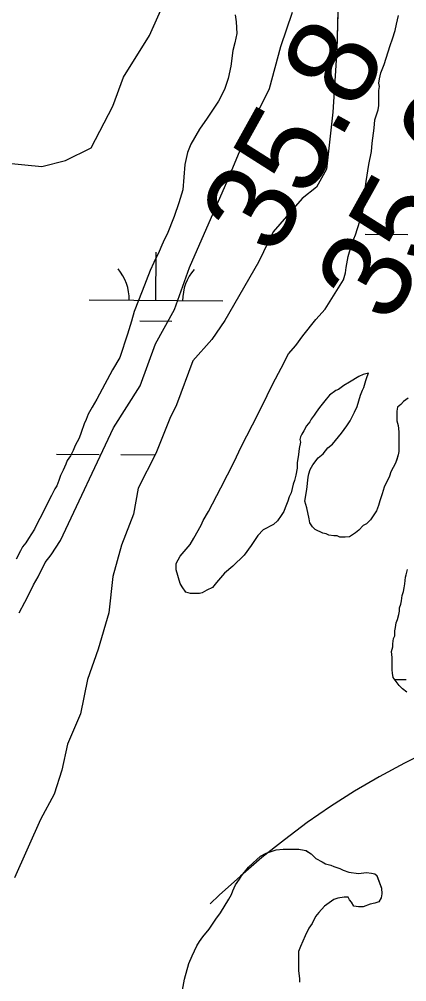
# Model space of a CAD drawing. Extents: x 3271442 to 3309282, y 752266 to 777610.
# Drawn here: x 3286138 to 3286428, y 766789 to 767508 of the extents above; entities that cross this region are included whole.
import ezdxf

# ---------------------------------------------------------------- set-up
doc = ezdxf.new("R2010")
doc.units = 0
for name, color, linetype in [('V-RIVR-RANG', 7, 'Continuous'), ('V-SITE-VEGE', 7, 'Continuous'), ('V-TOPO-MAJR', 7, 'Continuous'), ('V-TOPO-SHOR', 7, 'Continuous'), ('V-WETL-SWMP', 7, 'Continuous')]:
    doc.layers.add(name, color=color, linetype=linetype)

msp = doc.modelspace()

# ---------------------------------------------------------------- linework, layer by layer
at = {"layer": 'V-SITE-VEGE'}
for points in [[(3286126.68, 767401.28), (3286154.51, 767398.32), (3286172.15, 767402.8), (3286191.51, 767412.38), (3286207.55, 767443.57), (3286215.59, 767465.13), (3286235.04, 767496.31), (3286256.84, 767545.09), (3286266.64, 767579.72), (3286270.24, 767625.74), (3286269.25, 767663.82), (3286263.19, 767709.88), (3286273.59, 767750.75), (3286293.08, 767793.86), (3286306.85, 767823.93), (3286325.76, 767863.63), (3286346.42, 767912.99), (3286355.65, 767945.34)], [(3286376.57, 767531.75), (3286375.25, 767485.72), (3286372.22, 767439.13), (3286367.5, 767396.53), (3286360.05, 767382.92), (3286349.22, 767374.44), (3286327.52, 767349.52), (3286316.63, 767326.84), (3286291.45, 767283.18), (3286281.73, 767269.01), (3286267.46, 767253.16), (3286255.39, 767220.25), (3286250.23, 767210.04), (3286239.9, 767183.94), (3286226.72, 767157.85), (3286223.23, 767138.54), (3286214.04, 767115.28), (3286207.7, 767092), (3286204.74, 767064.74), (3286196.68, 767037.49), (3286188.63, 767014.79), (3286183.41, 766989.24), (3286173.66, 766966.55), (3286169.6, 766947.24), (3286163.84, 766929.08), (3286153.54, 766910.37), (3286134.04, 766866.69)], [(3286299.12, 767511.92), (3286300.07, 767506.56), (3286300.52, 767497.79), (3286299.03, 767490.98), (3286297.55, 767485.14), (3286296.04, 767473.45), (3286294.05, 767464.2), (3286291.1, 767455.93), (3286286.68, 767447.18), (3286278.34, 767434.55), (3286272.46, 767426.29), (3286266.08, 767415.11), (3286263.62, 767408.79), (3286261.64, 767400.03), (3286260.1, 767381.03), (3286257.14, 767371.3), (3286253.68, 767361.08), (3286248.27, 767347.95), (3286246.31, 767344.07), (3286244.34, 767339.69), (3286242.37, 767334.83), (3286238.44, 767326.56), (3286235.49, 767320.73), (3286229.58, 767305.16), (3286223.68, 767290.08), (3286221.7, 767282.78), (3286218.73, 767273.05), (3286212.82, 767255.54), (3286207.42, 767246.3), (3286197.6, 767228.32), (3286195.64, 767224.43), (3286192.21, 767218.6), (3286189.26, 767213.25), (3286187.78, 767209.36), (3286186.31, 767205.95), (3286183.85, 767199.63), (3286182.37, 767195.26), (3286179.42, 767189.91), (3286177.95, 767186.02), (3286175.98, 767182.13), (3286173.53, 767178.73), (3286172.54, 767175.81), (3286170.58, 767171.43), (3286168.61, 767167.54), (3286167.14, 767163.65), (3286165.66, 767159.76), (3286164.19, 767157.33), (3286161.73, 767152.47), (3286156.82, 767142.74), (3286154.36, 767137.4), (3286151.91, 767133.02), (3286148.96, 767127.19), (3286144.55, 767120.38), (3286142.59, 767116.98), (3286140.14, 767114.07), (3286138.67, 767111.15), (3286135.23, 767104.83)], [(3286137.5, 767064.87), (3286141.92, 767072.65), (3286144.38, 767077.51), (3286148.31, 767085.78), (3286151.74, 767091.61), (3286157.14, 767102.31), (3286161.55, 767108.13), (3286168.42, 767118.82), (3286208.16, 767203.16), (3286228.09, 767234.5), (3286239.49, 767265.84), (3286253.73, 767291.49), (3286265.12, 767322.83), (3286293.6, 767388.36), (3286307.84, 767422.55), (3286324.93, 767456.74), (3286333.47, 767488.08), (3286342.01, 767513.72)], [(3286258.01, 767086.63), (3286255.13, 767096.87), (3286255.15, 767101.74), (3286258.09, 767107.09), (3286265.44, 767115.83), (3286268.38, 767120.69), (3286273.78, 767130.41), (3286275.25, 767133.81), (3286279.18, 767140.62), (3286288.51, 767158.12), (3286298.33, 767177.57), (3286303.73, 767188.75), (3286312.08, 767205.28), (3286318.96, 767218.4), (3286327.31, 767235.91), (3286333.69, 767247.57), (3286339.09, 767258.27), (3286344.48, 767264.58), (3286349.87, 767271.87), (3286359.66, 767284), (3286366.51, 767291.77), (3286380.24, 767313.64), (3286381.73, 767318.99), (3286382.23, 767322.89), (3286383.72, 767331.16), (3286384.71, 767334.57), (3286385.7, 767337.49), (3286386.69, 767341.38), (3286389.15, 767347.22), (3286392.6, 767357.43), (3286394.57, 767363.76), (3286396.06, 767371.06), (3286396.1, 767379.83), (3286397.1, 767387.13), (3286399.1, 767399.79), (3286401.09, 767409.53), (3286401.61, 767415.86), (3286403.11, 767427.06), (3286403.63, 767433.39), (3286406.09, 767440.68), (3286406.59, 767444.09), (3286406.61, 767448.48), (3286406.64, 767455.3), (3286407.14, 767458.22), (3286406.66, 767460.65), (3286407.16, 767464.06), (3286408.15, 767468.45), (3286410.62, 767474.77), (3286415.06, 767488.88), (3286417.03, 767493.74), (3286419, 767500.07), (3286419.99, 767504.93), (3286421.48, 767511.26)], [(3286421.67, 767199.96), (3286421.61, 767185.34), (3286421.12, 767182.91), (3286420.13, 767179.51), (3286419.14, 767176.58), (3286415.71, 767170.27), (3286414.72, 767166.86), (3286410.79, 767158.59), (3286409.3, 767153.73), (3286407.33, 767148.38), (3286406.35, 767144.97), (3286404.87, 767141.08), (3286403.4, 767138.65), (3286400.46, 767134.28), (3286397.52, 767131.37), (3286395.08, 767129.92), (3286391.66, 767126.52), (3286389.21, 767124.58), (3286384.81, 767121.68), (3286381.4, 767121.2), (3286377.51, 767121.22), (3286375.56, 767122.2), (3286373.13, 767122.21), (3286369.23, 767122.71), (3286367.29, 767123.7), (3286364.85, 767124.19), (3286359.02, 767127.14), (3286357.08, 767129.09), (3286355.14, 767132.03), (3286354.67, 767134.95), (3286352.75, 767143.24), (3286351.31, 767148.12), (3286352.81, 767156.88), (3286353.82, 767166.13), (3286354.31, 767168.57), (3286355.3, 767171.97), (3286357.27, 767175.38), (3286361.19, 767180.72), (3286365.1, 767183.62), (3286368.52, 767188), (3286371.95, 767190.91), (3286378.8, 767199.16), (3286382.72, 767204.5), (3286385.17, 767208.39), (3286388.61, 767214.71), (3286390.57, 767219.08), (3286393.04, 767227.36), (3286394.52, 767231.25), (3286395.5, 767233.19), (3286396.98, 767238.55), (3286397.97, 767241.46), (3286398.96, 767243.9), (3286395.06, 767242.94), (3286391.64, 767241.49), (3286384.8, 767237.13), (3286380.41, 767234.72), (3286376.5, 767231.81), (3286374.54, 767230.84), (3286369.66, 767227.45), (3286367.21, 767224.54), (3286362.31, 767218.23), (3286359.86, 767214.83), (3286358.39, 767212.4), (3286355.94, 767209.48), (3286354.96, 767207.54), (3286352.51, 767204.63), (3286350.55, 767200.74), (3286349.08, 767198.31), (3286348.1, 767196.36), (3286347.6, 767194.41), (3286348.08, 767192.46), (3286347.09, 767187.6), (3286346.58, 767183.21), (3286345.58, 767176.88), (3286345.56, 767172.99), (3286344.57, 767167.63), (3286343.58, 767163.74), (3286342.59, 767160.82), (3286341.11, 767154.49), (3286339.63, 767151.58), (3286338.64, 767148.17), (3286336.68, 767143.31), (3286335.69, 767140.39), (3286333.73, 767137.47), (3286330.79, 767133.59), (3286327.85, 767130.68), (3286320.04, 767126.81), (3286316.13, 767122.44), (3286311.23, 767115.16), (3286305.84, 767107.87), (3286297.52, 767099.62), (3286291.17, 767094.29), (3286285.29, 767087.49), (3286282.36, 767083.61), (3286277.96, 767081.68), (3286274.55, 767079.74), (3286272.6, 767079.26), (3286265.77, 767079.29), (3286262.37, 767080.28), (3286259.46, 767084.19), (3286258.01, 767086.63)], [(3286428.6, 767225.26), (3286425.18, 767222.84), (3286423.22, 767220.41), (3286420.78, 767218.47), (3286420.28, 767215.55), (3286420.25, 767208.25), (3286421.21, 767204.83), (3286421.67, 767199.96)], [(3286427.7, 767005.55), (3286424.3, 767008), (3286421.88, 767010.45), (3286417.52, 767016.31), (3286417.04, 767019.73), (3286416.56, 767022.16), (3286416.6, 767031.42), (3286416.14, 767035.81), (3286417.12, 767039.21), (3286417.13, 767041.65), (3286417.63, 767045.54), (3286418.62, 767047.49), (3286418.63, 767051.38), (3286419.13, 767053.82), (3286419.63, 767057.23), (3286420.61, 767059.66), (3286421.6, 767063.55), (3286422.1, 767065.99), (3286422.11, 767068.42), (3286423.1, 767071.34), (3286423.59, 767073.78), (3286424.1, 767077.67), (3286425.08, 767080.59), (3286425.58, 767083.51), (3286426.08, 767086.43), (3286426.59, 767091.3), (3286427.09, 767093.25), (3286428.08, 767097.14)], [(3286259.69, 766782.63), (3286261.19, 766790.91), (3286264.65, 766802.58), (3286267.11, 766808.42), (3286270.55, 766815.71), (3286272.51, 766819.11), (3286274.96, 766822.52), (3286279.85, 766828.34), (3286284.76, 766835.63), (3286288.18, 766840.48), (3286294.56, 766850.69), (3286296.52, 766854.09), (3286297.51, 766857.01), (3286299.48, 766861.39), (3286302.42, 766865.76), (3286303.89, 766868.19), (3286309.27, 766874.5), (3286312.7, 766877.9), (3286318.08, 766882.75), (3286322.47, 766885.17), (3286329.79, 766887.57), (3286335.15, 766888.04), (3286341.97, 766888.01), (3286346.84, 766887.99), (3286352.2, 766886.99), (3286356.08, 766884.54), (3286359.48, 766881.12), (3286364.34, 766878.66), (3286366.77, 766877.19), (3286370.66, 766876.2), (3286373.09, 766875.21), (3286377.47, 766873.74), (3286379.9, 766872.27), (3286384.28, 766870.79), (3286391.58, 766869.78), (3286397.44, 766870.73), (3286401.33, 766870.23), (3286403.76, 766869.73), (3286405.22, 766868.26), (3286408.59, 766858.99), (3286409.06, 766854.61), (3286408.56, 766851.69), (3286406.6, 766848.77), (3286403.67, 766847.81), (3286400.26, 766846.85), (3286394.89, 766844.92), (3286391.48, 766844.94), (3286388.08, 766845.44), (3286386.14, 766848.37), (3286384.68, 766850.32), (3286383.72, 766852.28), (3286380.79, 766852.29), (3286375.92, 766851.33), (3286372.99, 766850.37), (3286366.15, 766845.53), (3286361.75, 766840.67), (3286359.3, 766837.76), (3286356.84, 766832.41), (3286354.39, 766829.01), (3286351.45, 766823.18), (3286348, 766815.4), (3286346.53, 766811.51), (3286346.47, 766797.38), (3286347.42, 766791.04), (3286347.41, 766788.6)]]:
    msp.add_lwpolyline(points, dxfattribs=at)
at = {"layer": 'V-TOPO-MAJR'}
msp.add_lwpolyline([(3286444.26, 766961.62), (3286425.84, 766952.28), (3286407.03, 766942.2), (3286388.57, 766931.54), (3286370.64, 766920.02), (3286353.05, 766907.94), (3286335.99, 766895.1), (3286319.27, 766881.85), (3286303.07, 766867.96), (3286287.23, 766853.65), (3286280.48, 766847.32)], dxfattribs=at)
at = {"layer": 'V-TOPO-SHOR'}
for points in [[(3286126.68, 767401.28), (3286154.51, 767398.32), (3286172.15, 767402.8), (3286191.51, 767412.38), (3286207.55, 767443.57), (3286215.59, 767465.13), (3286235.04, 767496.31), (3286256.84, 767545.09), (3286266.64, 767579.72), (3286270.24, 767625.74), (3286269.25, 767663.82), (3286263.19, 767709.88), (3286273.59, 767750.75), (3286293.08, 767793.86), (3286306.85, 767823.93), (3286325.76, 767863.63), (3286346.42, 767912.99), (3286355.65, 767945.34)], [(3286376.57, 767531.75), (3286375.25, 767485.72), (3286372.22, 767439.13), (3286367.5, 767396.53), (3286360.05, 767382.92), (3286349.22, 767374.44), (3286327.52, 767349.52), (3286316.63, 767326.84), (3286291.45, 767283.18), (3286281.73, 767269.01), (3286267.46, 767253.16), (3286255.39, 767220.25), (3286250.23, 767210.04), (3286239.9, 767183.94), (3286226.72, 767157.85), (3286223.23, 767138.54), (3286214.04, 767115.28), (3286207.7, 767092), (3286204.74, 767064.74), (3286196.68, 767037.49), (3286188.63, 767014.79), (3286183.41, 766989.24), (3286173.66, 766966.55), (3286169.6, 766947.24), (3286163.84, 766929.08), (3286153.54, 766910.37), (3286134.04, 766866.69)]]:
    msp.add_lwpolyline(points, dxfattribs=at)
at = {"layer": 'V-WETL-SWMP'}
for p, q in [((3286235.04, 767496.31), (3286256.84, 767545.1)), ((3286376.57, 767531.75), (3286375.25, 767485.72)), ((3286215.59, 767465.13), (3286235.04, 767496.31)), ((3286375.25, 767485.72), (3286372.22, 767439.13)), ((3286207.55, 767443.57), (3286215.59, 767465.13)), ((3286191.51, 767412.38), (3286207.55, 767443.57)), ((3286372.22, 767439.13), (3286367.5, 767396.53)), ((3286172.15, 767402.8), (3286191.51, 767412.38)), ((3286126.68, 767401.28), (3286154.51, 767398.32)), ((3286154.51, 767398.32), (3286172.15, 767402.8)), ((3286367.5, 767396.53), (3286360.05, 767382.92)), ((3286360.05, 767382.92), (3286349.22, 767374.44)), ((3286349.22, 767374.44), (3286327.52, 767349.52)), ((3286327.52, 767349.52), (3286316.63, 767326.84)), ((3286396.35, 767347.9), (3286428.35, 767347.63)), ((3286239.9, 767298.28), (3286240.19, 767334.28)), ((3286316.63, 767326.84), (3286291.45, 767283.18)), ((3286189.9, 767298.69), (3286289.9, 767297.87)), ((3286227.77, 767282.95), (3286251.77, 767282.75)), ((3286291.45, 767283.18), (3286281.73, 767269.01)), ((3286281.73, 767269.01), (3286267.46, 767253.16)), ((3286267.46, 767253.16), (3286255.39, 767220.24)), ((3286255.39, 767220.24), (3286250.23, 767210.04)), ((3286250.23, 767210.04), (3286239.9, 767183.94)), ((3286239.9, 767183.94), (3286226.72, 767157.85)), ((3286165.54, 767183.45), (3286197.54, 767183.19)), ((3286213.54, 767183.06), (3286239.35, 767182.85)), ((3286226.72, 767157.85), (3286223.23, 767138.54)), ((3286223.23, 767138.54), (3286214.04, 767115.28)), ((3286214.04, 767115.28), (3286207.7, 767092)), ((3286207.7, 767092), (3286204.74, 767064.74)), ((3286204.74, 767064.74), (3286196.68, 767037.49)), ((3286196.68, 767037.49), (3286188.63, 767014.79)), ((3286188.63, 767014.79), (3286183.41, 766989.24)), ((3286418.59, 767014.93), (3286427.11, 767014.86)), ((3286183.41, 766989.24), (3286173.66, 766966.55)), ((3286173.66, 766966.55), (3286169.6, 766947.24)), ((3286169.6, 766947.24), (3286163.84, 766929.08)), ((3286163.84, 766929.08), (3286153.54, 766910.37)), ((3286153.54, 766910.37), (3286134.04, 766866.69))]:
    msp.add_line(p, q, dxfattribs=at)
for points in [[(3286258.01, 767086.63), (3286255.13, 767096.87), (3286255.15, 767101.74), (3286258.09, 767107.09), (3286265.44, 767115.83), (3286268.38, 767120.69), (3286273.78, 767130.41), (3286275.25, 767133.81), (3286279.18, 767140.62), (3286288.51, 767158.12), (3286298.33, 767177.57), (3286303.73, 767188.75), (3286312.08, 767205.28), (3286318.96, 767218.4), (3286327.31, 767235.91), (3286333.69, 767247.57), (3286339.09, 767258.27), (3286344.48, 767264.58), (3286349.87, 767271.87), (3286359.66, 767284.01), (3286366.51, 767291.77), (3286380.24, 767313.64), (3286381.72, 767318.99), (3286382.23, 767322.89), (3286383.72, 767331.16), (3286384.71, 767334.57), (3286385.7, 767337.49), (3286386.69, 767341.38), (3286389.15, 767347.22), (3286392.6, 767357.43), (3286394.57, 767363.76), (3286396.06, 767371.06), (3286396.1, 767379.83), (3286397.1, 767387.13), (3286399.1, 767399.79), (3286401.09, 767409.53), (3286401.61, 767415.86), (3286403.11, 767427.06), (3286403.63, 767433.39), (3286406.09, 767440.68), (3286406.59, 767444.09), (3286406.61, 767448.48), (3286406.64, 767455.3), (3286407.14, 767458.22), (3286406.66, 767460.66), (3286407.16, 767464.06), (3286408.15, 767468.44), (3286410.62, 767474.77), (3286415.06, 767488.88), (3286417.03, 767493.74), (3286419, 767500.07), (3286419.99, 767504.93), (3286421.48, 767511.26)], [(3286421.67, 767199.96), (3286421.61, 767185.34), (3286421.12, 767182.91), (3286420.13, 767179.5), (3286419.14, 767176.58), (3286415.71, 767170.27), (3286414.72, 767166.86), (3286410.79, 767158.59), (3286409.31, 767153.73), (3286407.33, 767148.38), (3286406.35, 767144.97), (3286404.87, 767141.08), (3286403.4, 767138.65), (3286400.46, 767134.28), (3286397.52, 767131.37), (3286395.08, 767129.92), (3286391.66, 767126.52), (3286389.21, 767124.58), (3286384.82, 767121.68), (3286381.4, 767121.2), (3286377.51, 767121.22), (3286375.56, 767122.2), (3286373.13, 767122.21), (3286369.23, 767122.71), (3286367.29, 767123.7), (3286364.85, 767124.19), (3286359.02, 767127.14), (3286357.08, 767129.1), (3286355.14, 767132.03), (3286354.67, 767134.95), (3286352.75, 767143.24), (3286351.31, 767148.12), (3286352.81, 767156.88), (3286353.82, 767166.13), (3286354.32, 767168.57), (3286355.3, 767171.97), (3286357.27, 767175.38), (3286361.19, 767180.72), (3286365.1, 767183.63), (3286368.52, 767188), (3286371.95, 767190.91), (3286378.8, 767199.16), (3286382.72, 767204.5), (3286385.17, 767208.39), (3286388.61, 767214.71), (3286390.57, 767219.08), (3286393.04, 767227.36), (3286394.52, 767231.25), (3286395.5, 767233.19), (3286396.98, 767238.55), (3286397.97, 767241.46), (3286398.96, 767243.9), (3286395.06, 767242.94), (3286391.64, 767241.49), (3286384.8, 767237.13), (3286380.41, 767234.72), (3286376.5, 767231.81), (3286374.54, 767230.84), (3286369.66, 767227.45), (3286367.21, 767224.54), (3286362.31, 767218.23), (3286359.86, 767214.83), (3286358.39, 767212.4), (3286355.95, 767209.48), (3286354.96, 767207.54), (3286352.52, 767204.63), (3286350.55, 767200.74), (3286349.08, 767198.31), (3286348.1, 767196.36), (3286347.6, 767194.42), (3286348.08, 767192.46), (3286347.09, 767187.6), (3286346.58, 767183.21), (3286345.58, 767176.89), (3286345.56, 767172.99), (3286344.57, 767167.63), (3286343.58, 767163.74), (3286342.59, 767160.82), (3286341.1, 767154.49), (3286339.63, 767151.58), (3286338.64, 767148.17), (3286336.68, 767143.31), (3286335.69, 767140.39), (3286333.73, 767137.47), (3286330.79, 767133.59), (3286327.85, 767130.68), (3286320.04, 767126.81), (3286316.13, 767122.44), (3286311.23, 767115.16), (3286305.84, 767107.87), (3286297.52, 767099.62), (3286291.17, 767094.29), (3286285.29, 767087.49), (3286282.36, 767083.61), (3286277.96, 767081.68), (3286274.54, 767079.74), (3286272.6, 767079.26), (3286265.77, 767079.29), (3286262.37, 767080.28), (3286259.46, 767084.19), (3286258.01, 767086.63)], [(3286428.6, 767225.26), (3286425.18, 767222.84), (3286423.22, 767220.41), (3286420.77, 767218.47), (3286420.28, 767215.55), (3286420.25, 767208.25), (3286421.21, 767204.83), (3286421.67, 767199.96)], [(3286427.7, 767005.55), (3286424.3, 767008), (3286421.88, 767010.45), (3286417.52, 767016.31), (3286417.04, 767019.73), (3286416.56, 767022.16), (3286416.6, 767031.42), (3286416.13, 767035.81), (3286417.12, 767039.21), (3286417.13, 767041.65), (3286417.63, 767045.54), (3286418.62, 767047.49), (3286418.63, 767051.39), (3286419.13, 767053.82), (3286419.63, 767057.23), (3286420.61, 767059.66), (3286421.6, 767063.55), (3286422.1, 767065.99), (3286422.11, 767068.42), (3286423.1, 767071.34), (3286423.6, 767073.78), (3286424.1, 767077.67), (3286425.08, 767080.59), (3286425.58, 767083.51), (3286426.08, 767086.43), (3286426.59, 767091.3), (3286427.08, 767093.25), (3286428.08, 767097.14)], [(3286259.69, 766782.63), (3286261.19, 766790.91), (3286264.65, 766802.58), (3286267.11, 766808.42), (3286270.55, 766815.71), (3286272.51, 766819.11), (3286274.96, 766822.52), (3286279.85, 766828.34), (3286284.75, 766835.63), (3286288.19, 766840.49), (3286294.56, 766850.69), (3286296.52, 766854.09), (3286297.51, 766857.01), (3286299.48, 766861.39), (3286302.42, 766865.76), (3286303.89, 766868.19), (3286309.27, 766874.5), (3286312.7, 766877.9), (3286318.08, 766882.75), (3286322.47, 766885.17), (3286329.79, 766887.57), (3286335.15, 766888.04), (3286341.97, 766888.01), (3286346.84, 766887.99), (3286352.19, 766886.99), (3286356.08, 766884.54), (3286359.48, 766881.12), (3286364.34, 766878.66), (3286366.77, 766877.19), (3286370.66, 766876.2), (3286373.09, 766875.22), (3286377.47, 766873.74), (3286379.9, 766872.27), (3286384.28, 766870.79), (3286391.58, 766869.78), (3286397.43, 766870.73), (3286401.33, 766870.23), (3286403.76, 766869.73), (3286405.22, 766868.27), (3286408.59, 766858.99), (3286409.06, 766854.61), (3286408.56, 766851.69), (3286406.6, 766848.77), (3286403.67, 766847.81), (3286400.26, 766846.85), (3286394.89, 766844.92), (3286391.48, 766844.94), (3286388.08, 766845.44), (3286386.14, 766848.37), (3286384.68, 766850.32), (3286383.72, 766852.28), (3286380.79, 766852.29), (3286375.92, 766851.33), (3286372.99, 766850.37), (3286366.15, 766845.53), (3286361.75, 766840.67), (3286359.3, 766837.76), (3286356.84, 766832.41), (3286354.39, 766829.01), (3286351.45, 766823.18), (3286348, 766815.4), (3286346.53, 766811.51), (3286346.47, 766797.38), (3286347.42, 766791.04), (3286347.41, 766788.6)]]:
    msp.add_lwpolyline(points, dxfattribs=at)
for centre, start, end in [((3286184.66, 767299.21), 358.75626, 40.29991), ((3286295.14, 767298.3), 138.75625, 180.29991)]:
    msp.add_arc(centre, 35.25, start, end, dxfattribs=at)

# ---------------------------------------------------------------- texts
at = {"layer": 'V-RIVR-RANG'}
for s, p in [('35.8', (3286328.75, 767329.86)), ('35.0', (3286414.85, 767278.94))]:
    msp.add_text(s, height=67, rotation=60.91833, dxfattribs=at).set_placement(p)

doc.saveas('drawing.dxf')
